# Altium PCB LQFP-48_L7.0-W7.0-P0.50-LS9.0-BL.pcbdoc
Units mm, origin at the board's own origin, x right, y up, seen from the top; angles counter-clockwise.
Board outline 22.7 x 22.7 mm, 2 copper layers (Top Layer, Bottom Layer), stack 0.07 mm thick; 1 components, 0 nets, 48 pads, 0 vias.
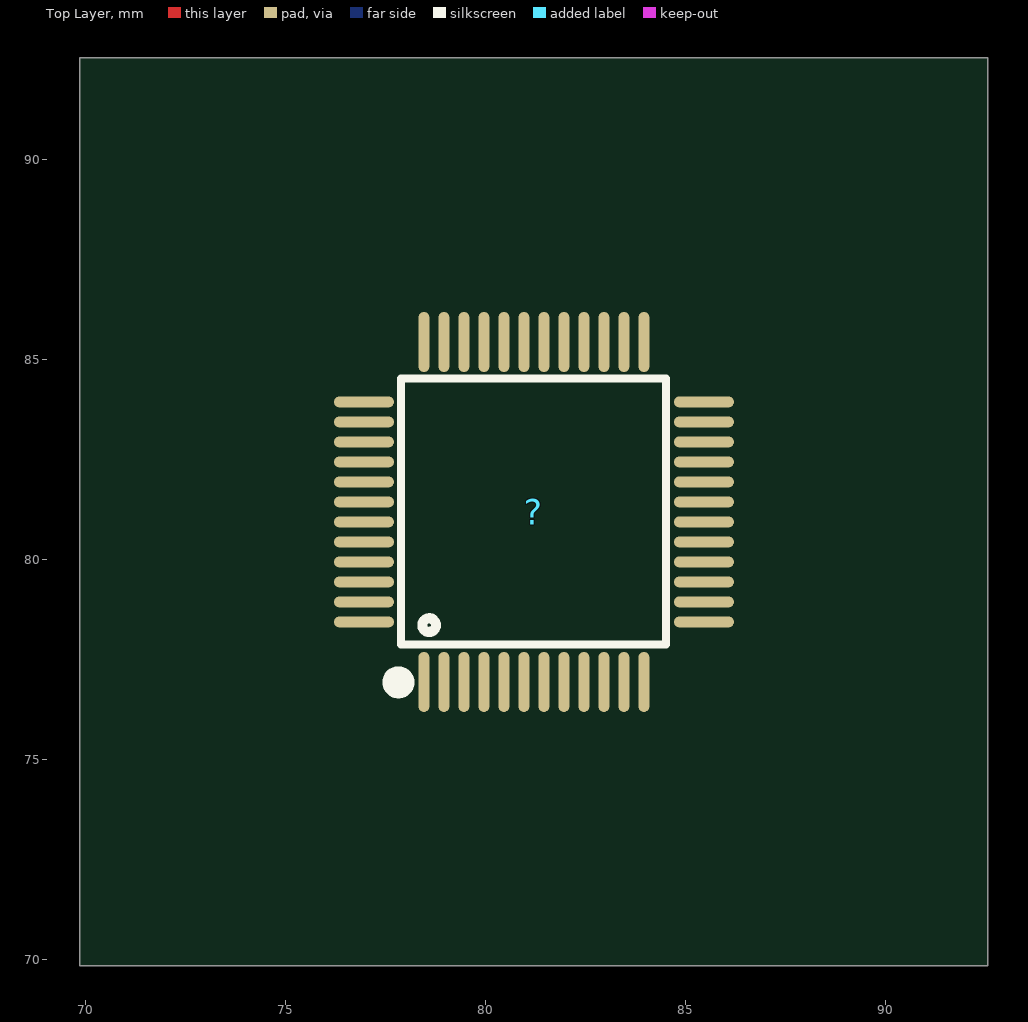
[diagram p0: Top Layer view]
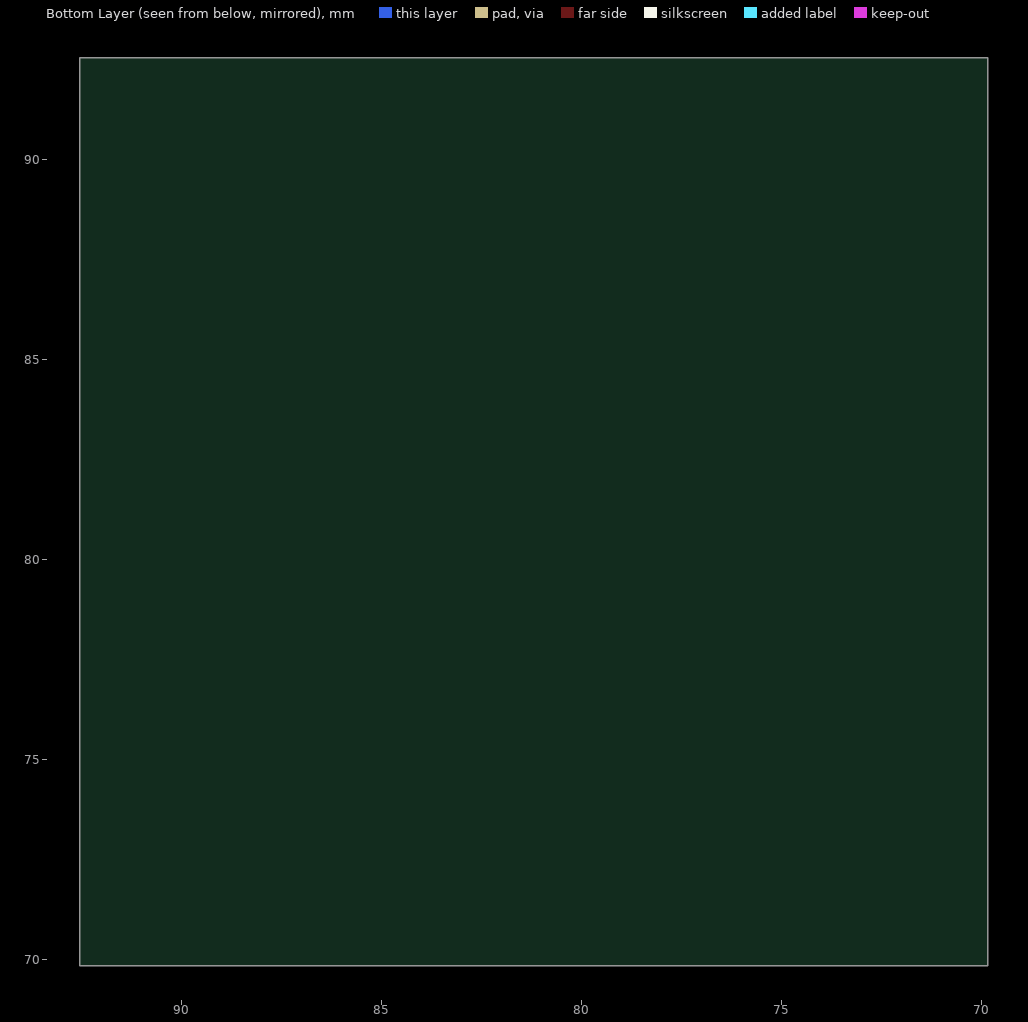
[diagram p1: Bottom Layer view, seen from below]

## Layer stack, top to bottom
Top Solder Mask Layer: solder mask 0.01, Dk 3.3
Top Layer: signal copper 0.035
Bottom Layer: signal copper 0.035
Bottom Solder Mask Layer: solder mask 0.01, Dk 3.3

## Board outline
92.55,69.85 69.85,69.85 69.85,92.55 92.55,92.55

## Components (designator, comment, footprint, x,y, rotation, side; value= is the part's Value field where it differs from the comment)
? "LQFP-48_L7.0-W7.0-P0.50-LS9.0-BL" LQFP-48_L7.0-W7.0-P0.50-LS9.0-BL 81.2,81.2 r0 top

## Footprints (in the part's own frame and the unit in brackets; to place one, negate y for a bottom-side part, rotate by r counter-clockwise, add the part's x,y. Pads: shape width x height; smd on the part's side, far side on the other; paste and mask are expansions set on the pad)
LQFP-48_L7.0-W7.0-P0.50-LS9.0-BL [mm]
  oval 0.27x1.5 smd paste+0 mask+0.05: 1(-2.75,-4.25) 2(-2.25,-4.25) 3(-1.75,-4.25) 4(-1.25,-4.25) 5(-0.75,-4.25) 6(-0.25,-4.25) 7(0.25,-4.25) 8(0.75,-4.25) 9(1.25,-4.25) 10(1.75,-4.25) 11(2.25,-4.25) 12(2.75,-4.25) 25(2.75,4.25) 26(2.25,4.25) 27(1.75,4.25) 28(1.25,4.25) 29(0.75,4.25) 30(0.25,4.25) 31(-0.25,4.25) 32(-0.75,4.25) 33(-1.25,4.25) 34(-1.75,4.25) 35(-2.25,4.25) 36(-2.75,4.25)
  oval 1.5x0.27 smd paste+0 mask+0.05: 13(4.25,-2.75) 14(4.25,-2.25) 15(4.25,-1.75) 16(4.25,-1.25) 17(4.25,-0.75) 18(4.25,-0.25) 19(4.25,0.25) 20(4.25,0.75) 21(4.25,1.25) 22(4.25,1.75) 23(4.25,2.25) 24(4.25,2.75) 37(-4.25,2.75) 38(-4.25,2.25) 39(-4.25,1.75) 40(-4.25,1.25) 41(-4.25,0.75) 42(-4.25,0.25) 43(-4.25,-0.25) 44(-4.25,-0.75) 45(-4.25,-1.25) 46(-4.25,-1.75) 47(-4.25,-2.25) 48(-4.25,-2.75)
  silkscreen extent -3.59,-4.46 3.3,3.34

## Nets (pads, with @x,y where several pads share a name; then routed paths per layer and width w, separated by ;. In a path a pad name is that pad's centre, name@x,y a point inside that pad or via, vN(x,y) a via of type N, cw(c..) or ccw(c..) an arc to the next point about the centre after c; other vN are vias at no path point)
pads on no net: ?.1 ?.2 ?.3 ?.4 ?.5 ?.6 ?.7 ?.8 ?.9 ?.10 ?.11 ?.12 ?.13 ?.14 ?.15 ?.16 ?.17 ?.18 ?.19 ?.20 ?.21 ?.22 ?.23 ?.24 ?.25 ?.26 ?.27 ?.28 ?.29 ?.30 ?.31 ?.32 ?.33 ?.34 ?.35 ?.36 ?.37 ?.38 ?.39 ?.40 ?.41 ?.42 ?.43 ?.44 ?.45 ?.46 ?.47 ?.48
